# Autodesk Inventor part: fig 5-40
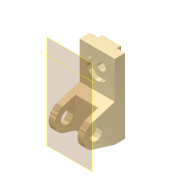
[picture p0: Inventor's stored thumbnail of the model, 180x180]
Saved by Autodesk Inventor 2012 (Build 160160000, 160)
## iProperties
Shininess: 65.0
Angle Display Precision: 2
Document Length Units: 11269
Document Angle Units: 11279
Document Time Units: 11290
Document Mass Units: 11283
Document Length Units Precision: 3
Document Angle Units Precision: 2
Created: 2001-11
Part Number: fig 5-40
Document SubType Name: Modeling
Designer: Renu Muthoo
Density: 1 g/cm^3
Material: Default
Density: 0.0
Volumn: 0.0
Area: 0.0
PropertySet Name: Model Information
Control State: 0
Master: False
Checked Out: False
Author: Renu Muthoo
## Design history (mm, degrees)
node "Sketch1"
sketch "Sketch2"
  geometry: L1 (33.257, 104.664)-(33.257, -75.336); L2 (33.257, -75.336)-(8.257, -75.336); L3 (8.257, -75.336)-(-45.451, -59.045); L4 (-45.451, -1.628)-(8.257, 14.664); L5 (8.257, 14.664)-(8.257, 104.664); L6 (8.257, 104.664)-(33.257, 104.664); C1 r 15 at (-36.743, -30.336); A1 r 30 centre (-36.743, -30.336) between (-45.451, -1.628) and (-45.451, -59.045)
  constraints: 12 end point, 2 centre point, 2 equal length, 2 parallel, 2 point on circle, 2 tangent, 1 coincident, 1 perpendicular, 1 vertical
  dimensions: "d0" = 180 distance of L1.start L1.end; "d1" = 30 radius of A1; "d2" = 25 distance of L5.end L1.start; "d3" = 45 distance from line of L2 A1.centre; "d4" = 70 distance from line of L1 A1.centre; "d5" = 30 diameter of C1
extrude "Extrusion1" new body sketch "Sketch2" distance "d6" = 85; taper "d7" = 0 deg
workplane "Work Plane1"
sketch "Sketch3"
  geometry: L1 (15, 62.364)-(70, 62.364); L2 (70, 62.364)-(70, -52.386); L3 (70, -52.386)-(15, -52.386); L4 (15, -52.386)-(15, 62.364); L5 (0, -45)-(0, -28.708) reference
  constraints: 8 end point, 2 parallel, 1 horizontal, 1 perpendicular
  dimensions: "d8" = 55 distance of L1.start L1.end; "d9" = 15 distance between parallel lines of L5 L4
extrude "Extrusion2" cut sketch "Sketch3" distance "d10" = 50; taper "d11" = 0 deg
sketch "Sketch4"
  geometry: L1 (0, 25)-(85, 25) reference; L2 (0, 0)-(0, 25) reference; L3 (20, 25)-(65, 25); L4 (65, 25)-(65, 35); L5 (65, 35)-(20, 35); L6 (20, 35)-(20, 25)
  constraints: 8 end point, 2 parallel, 1 horizontal, 1 perpendicular, 1 point on line
  dimensions: "d12" = 45 distance of L4.end L5.end; "d13" = 10 distance of L3.end L4.end; "d14" = 20 distance between parallel lines of L2 L6
extrude "Extrusion3" join sketch "Sketch4" stored distance "d15" = 50; taper "d16" = 0 deg
sketch "Sketch5"
  geometry: L1 (85, 0)-(85, 90) reference; L2 (0, 90)-(85, 90) reference; 1 further point
  dimensions: "d17" = 42 distance from line of L2 point (42.5, 48); "d18" = 42.5 distance from line of L1 point (42.5, 48)
hole "Hole1" sketch "Sketch5" at (42.5, 48) diameter "d19" = 20; stored, may be unused: countersink angle "d23" = 82 deg, drill point angle "d25" = 118 deg; dims "d20" = 6, "d21" = 50, "d22" = 10, "d24" = 8
workaxis "Work Axis1"
  workplane "Work Plane3"
body "Solid1"
